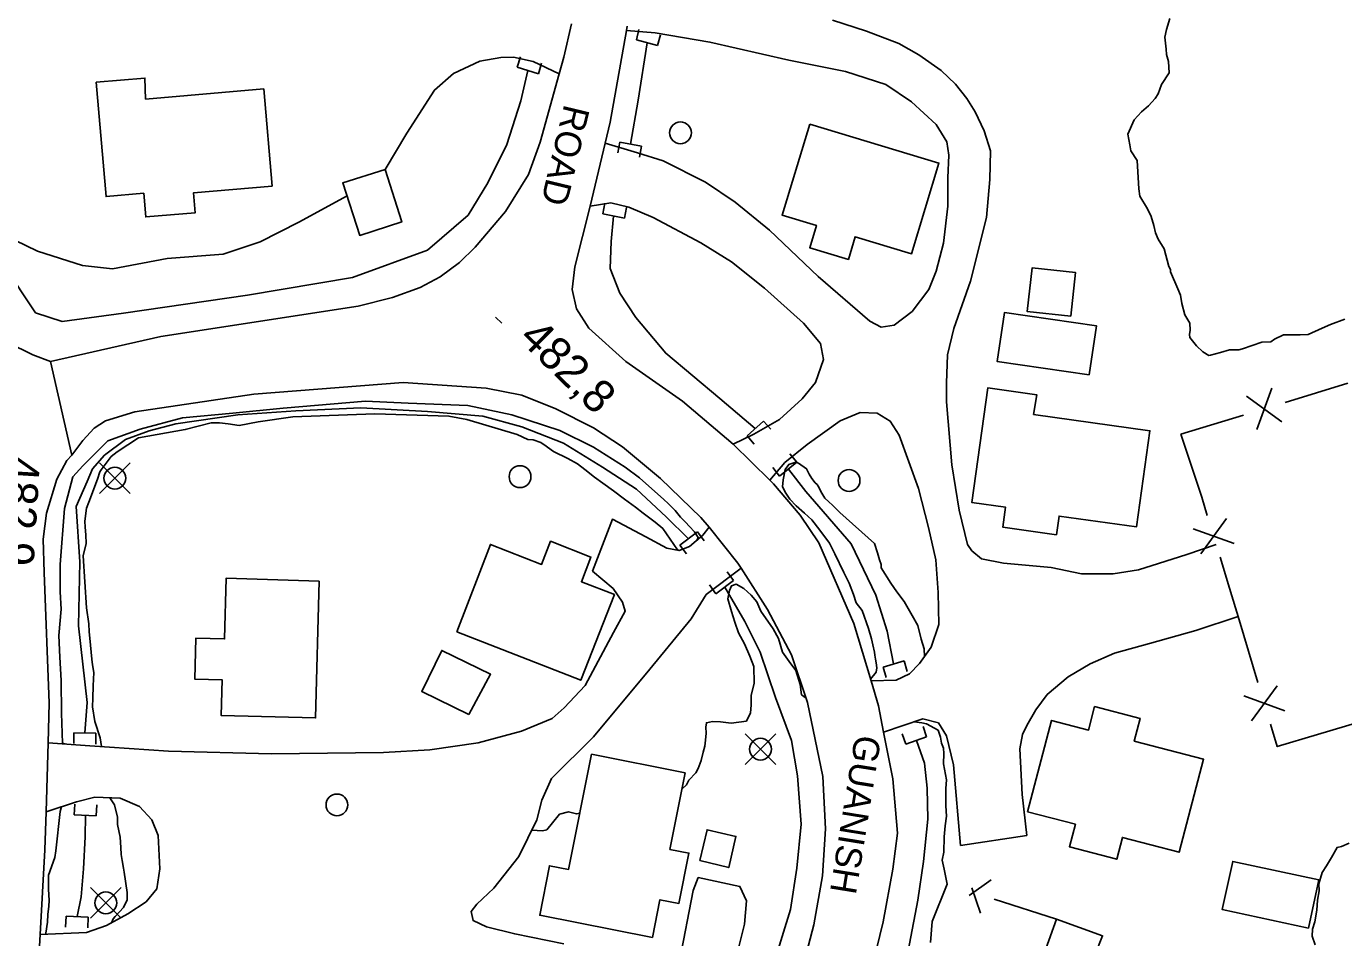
# Model space of a CAD drawing. Extents: x 642515 to 647219, y 6080136 to 6084356.
# Drawn here: x 643828.9 to 643949.6, y 6081952.1 to 6082035.7 of the extents above; entities that cross this region are included whole.
import ezdxf

# ---------------------------------------------------------------- set-up
doc = ezdxf.new("R2010")
doc.units = 0
for name, color, linetype in [('Level 19', 7, 'Continuous'), ('Level 2', 7, 'Continuous'), ('Level 21', 7, 'Continuous'), ('Level 26', 7, 'Continuous'), ('Level 3', 7, 'Continuous'), ('Level 31', 7, 'Continuous'), ('Level 36', 7, 'Continuous'), ('Level 37', 7, 'Continuous'), ('Level 4', 7, 'Continuous')]:
    doc.layers.add(name, color=color, linetype=linetype)

msp = doc.modelspace()

# ---------------------------------------------------------------- linework, layer by layer
at = {"layer": 'Level 19'}
for points in [[(643881.95, 6082024.95), (643884.92, 6082024.05), (643887.27, 6082023.33), (643891.14, 6082021.38), (643893.87, 6082019.55), (643897.01, 6082016.96), (643901.45, 6082012.74), (643906.21, 6082008.63), (643907.25, 6082008.08), (643908.42, 6082008.26), (643910.09, 6082009.52), (643911.6, 6082011.54), (643912.28, 6082013.23), (643912.95, 6082015.77), (643913.33, 6082019.18), (643913.35, 6082021.77), (643913.45, 6082023.84), (643913.26, 6082025.08), (643912.28, 6082026.65), (643910.02, 6082028.75), (643907.67, 6082030.33), (643903.96, 6082031.51), (643898.76, 6082032.57), (643891.54, 6082034.22), (643886.51, 6082035.05), (643883.89, 6082035.29)], [(643902.79, 6082036.23), (643905.88, 6082035.22), (643908.86, 6082034.08), (643910.7, 6082033.05), (643912.72, 6082031.61), (643914.04, 6082030.35), (643915.09, 6082029.03), (643915.84, 6082027.82), (643916.66, 6082026.08), (643917.25, 6082024.25), (643917.19, 6082021.62), (643916.89, 6082018.13), (643915.43, 6082012.31), (643913.88, 6082007.95), (643913.32, 6082005.54), (643913.22, 6082002.94), (643913.23, 6082001.25), (643913.71, 6081995.45), (643914.37, 6081991.32), (643915.15, 6081988.17), (643915.55, 6081987.58), (643916.44, 6081986.86), (643918.45, 6081986.44), (643922.8, 6081986.06), (643925.59, 6081985.48), (643928.5, 6081985.47), (643930.83, 6081985.83), (643932.66, 6081986.41), (643935.25, 6081987.24), (643937.93, 6081988.17)], [(643877.72, 6082031.3), (643875.35, 6082032.43), (643873.55, 6082032.82), (643872.38, 6082032.8), (643870.45, 6082032.46), (643868.04, 6082031.32), (643866.3, 6082029.82), (643863.76, 6082025.88), (643861.77, 6082022.52)], [(643822.51, 6082015.1), (643824.98, 6082017.33), (643826.4, 6082017.37), (643827.85, 6082016.07), (643829.93, 6082015.04), (643834.05, 6082013.72), (643836.78, 6082013.42), (643841.79, 6082014.37), (643846.92, 6082014.76), (643850.34, 6082015.9), (643853.88, 6082017.71), (643858.29, 6082020.11)], [(643893.66, 6081997.37), (643895.56, 6081998.28), (643897.91, 6081999.62), (643900, 6082001.5), (643901.21, 6082003.02), (643901.95, 6082005.12), (643901.67, 6082006.6), (643900.11, 6082008.46), (643896.53, 6082011.67), (643893.53, 6082014.06), (643890.72, 6082015.82), (643886.34, 6082018.13), (643884.1, 6082019.07), (643882.46, 6082019.47), (643880.56, 6082019.17)], [(643906.31, 6081975.65), (643908.61, 6081975.73), (643909.84, 6081976.32), (643910.76, 6081977.25), (643911.81, 6081978.76), (643912.51, 6081980.82), (643912.47, 6081983.77), (643912.23, 6081986.75), (643911.58, 6081989.71), (643910.66, 6081993.29), (643908.9, 6081998.18), (643908.06, 6081999.47), (643906.88, 6082000.21), (643905.3, 6082000.25), (643903.48, 6081999.51), (643900.44, 6081997.33), (643898.42, 6081995.69), (643897.04, 6081994.07)], [(643830.89, 6081969.99), (643834.71, 6081969.71), (643841.91, 6081969.23), (643851.36, 6081968.96), (643861.64, 6081969.09), (643865.88, 6081969.35), (643870.3, 6081969.99), (643874.26, 6081971.04), (643877.07, 6081972.2), (643878.19, 6081973.19), (643880.11, 6081975.23), (643882.72, 6081980.09), (643883.79, 6081982.05), (643883.54, 6081982.88), (643882.66, 6081984.13), (643880.79, 6081985.73), (643882.6, 6081990.47), (643885.68, 6081988.86), (643887.6, 6081987.82), (643888.71, 6081987.6), (643889.66, 6081987.97), (643890.9, 6081989.01), (643891.46, 6081989.74)], [(643894.4, 6081986), (643891.21, 6081983.57), (643889.83, 6081981.36), (643886.03, 6081976.72), (643880.86, 6081970.54), (643877.02, 6081966.71), (643876.15, 6081964.72), (643875.68, 6081962.92), (643874.04, 6081959.56), (643871.73, 6081956.65), (643870.19, 6081955.2), (643869.66, 6081954.52), (643869.83, 6081953.68), (643871.07, 6081953.1), (643873.66, 6081952.47), (643878.16, 6081951.57)], [(643907.46, 6081970.95), (643911.04, 6081972.19), (643912.48, 6081971.82), (643913.23, 6081970.61), (643913.86, 6081967.97), (643914.51, 6081960.57), (643920.57, 6081961.49), (643920.17, 6081965.23), (643919.94, 6081969.42), (643920.19, 6081970.73), (643920.57, 6081971.56), (643921.42, 6081973.02), (643922.44, 6081974.4), (643924.38, 6081976.04), (643926.38, 6081977.23), (643928.63, 6081978.2), (643931.83, 6081979.09), (643936.06, 6081980.28), (643939.94, 6081981.56)], [(643830.16, 6081952.4), (643834.4, 6081952.58), (643836.23, 6081953.24), (643838.2, 6081954.31), (643839.88, 6081955.41), (643840.87, 6081956.6), (643841.13, 6081958.43), (643840.97, 6081961.49), (643840.4, 6081962.92), (643839.28, 6081964.15), (643837.5, 6081964.91), (643835.18, 6081964.99), (643833.5, 6081964.58), (643830.7, 6081963.67)], [(643888.74, 6081949.98), (643890.01, 6081956.43), (643890.47, 6081957.63), (643894.29, 6081956.82), (643894.88, 6081955.51), (643894.72, 6081953.36), (643893.95, 6081950.29)]]:
    msp.add_lwpolyline(points, dxfattribs=at)
at = {"layer": 'Level 2'}
for points in [[(643933.7, 6082036.37), (643933.39, 6082035.36), (643933.22, 6082034.67), (643933.35, 6082033.56), (643933.37, 6082033.08), (643933.57, 6082032.45), (643933.62, 6082031.41), (643932.94, 6082030.34), (643932.62, 6082029.48), (643932.36, 6082029.03), (643931.74, 6082028.36), (643931.09, 6082027.81), (643930.43, 6082027.09), (643929.85, 6082025.78), (643930.02, 6082024.8), (643930.13, 6082024.24)], [(643930.13, 6082024.24), (643930.69, 6082023.35), (643930.86, 6082020.77), (643930.93, 6082020.09), (643931.63, 6082018.93), (643931.98, 6082018.23), (643932.23, 6082017.41), (643932.38, 6082016.73), (643932.61, 6082016.15), (643933.17, 6082015.26), (643933.61, 6082013.65), (643933.75, 6082013.37), (643933.76, 6082013.14), (643934.43, 6082011.61), (643934.66, 6082011.03), (643934.78, 6082010.24), (643935.07, 6082009.21), (643935.51, 6082008.44), (643935.54, 6082007.8), (643935.48, 6082007.4), (643935.53, 6082007.12), (643936.14, 6082006.36), (643936.72, 6082005.83), (643937.26, 6082005.5), (643937.43, 6082005.51), (643938.34, 6082005.75), (643939.17, 6082006), (643940.02, 6082006), (643940.34, 6082006.1), (643942.12, 6082006.71), (643942.93, 6082006.75), (643943.28, 6082006.97), (643944.11, 6082007.37), (643945.64, 6082007.38), (643946.36, 6082007.41), (643947.66, 6082008), (643948.41, 6082008.32), (643949.72, 6082008.83)], [(643832.44, 6081969.88), (643832.21, 6081969.94), (643832.11, 6081972.69), (643832.09, 6081975.68), (643831.98, 6081977.82), (643831.89, 6081979.81), (643832.09, 6081982.22), (643832.01, 6081983.81), (643832.01, 6081986.32), (643832.4, 6081991.45), (643833.15, 6081994.36), (643834.07, 6081995.37), (643836.37, 6081997.65), (643839.34, 6081998.72), (643843.2, 6081999.76), (643847.82, 6082000.21), (643852.43, 6082000.65), (643859.98, 6082001.29), (643863.9, 6082001.13), (643869.35, 6082000.9), (643873.38, 6082000.04), (643877.8, 6081998.6), (643880.86, 6081997.08), (643883.77, 6081995.24), (643885.1, 6081994.27)], [(643888.76, 6081987.62), (643888.57, 6081987.67), (643887.22, 6081989.64), (643886.51, 6081990.2), (643885.42, 6081991.02), (643884.71, 6081991.58), (643883.71, 6081992.32), (643882.7, 6081993.07), (643881.74, 6081993.78), (643880.95, 6081994.33), (643880.07, 6081995.04), (643879.4, 6081995.57), (643878.53, 6081996.04), (643877.21, 6081996.69), (643876.33, 6081997.32), (643876.08, 6081997.47), (643876.04, 6081997.5), (643875.34, 6081997.75), (643874.86, 6081997.8), (643873.87, 6081998.23), (643869.25, 6081999.62), (643867.62, 6081999.93), (643860.84, 6082000.13), (643853.32, 6081999.86), (643850.15, 6081999.41), (643848.4, 6081999.08), (643847.38, 6081999.22), (643846.61, 6081999.3), (643845.85, 6081999.3), (643843.46, 6081998.7), (643839.18, 6081997.95), (643837.23, 6081996.65), (643836.68, 6081996.23), (643835.74, 6081995.02), (643835.62, 6081994.81), (643835.41, 6081994.16), (643834.63, 6081992.05), (643834.42, 6081991.48), (643834.27, 6081990.31), (643834.3, 6081989.76), (643834.34, 6081989.04), (643834.37, 6081988.24), (643834.11, 6081987.11), (643834.42, 6081982.34), (643834.61, 6081980.88), (643834.65, 6081980.16), (643834.72, 6081979.56), (643834.89, 6081977.66), (643834.96, 6081977.14), (643835.07, 6081976.43), (643835.01, 6081975.19), (643834.99, 6081974.07), (643834.95, 6081973.27), (643835.17, 6081971.93), (643835.65, 6081970.44), (643835.77, 6081969.65), (643835.76, 6081969.64)], [(643911.2, 6081977.88), (643911.19, 6081978.61), (643910.91, 6081979.47), (643910.6, 6081980.73), (643910.08, 6081981.66), (643909.33, 6081982.94), (643908.68, 6081983.82), (643908.12, 6081984.63), (643907.25, 6081986.02), (643907.23, 6081986.34), (643907.09, 6081986.77), (643906.9, 6081987.39), (643906.62, 6081988.26), (643903.46, 6081991.08), (643902.78, 6081991.77), (643902.44, 6081992.07), (643902.07, 6081992.41), (643901.71, 6081993.03), (643901.54, 6081993.34), (643901.36, 6081993.65), (643901.19, 6081993.8), (643900.89, 6081994.22), (643900.63, 6081994.6), (643900.4, 6081995.11), (643899.65, 6081995.63), (643899.41, 6081995.7), (643898.77, 6081995.5), (643898.43, 6081995.05), (643898.24, 6081994.08), (643898.19, 6081993.44), (643898.5, 6081992.86), (643898.85, 6081992.32), (643899.44, 6081991.71), (643900.2, 6081991.03), (643900.87, 6081990.43), (643901.6, 6081989.47), (643902.51, 6081988.28), (643903, 6081987.31), (643903.8, 6081985.6), (643904.29, 6081984.62), (643904.71, 6081983.57), (643904.94, 6081982.82), (643905.5, 6081982.1), (643906.06, 6081980.45), (643906.35, 6081979.51), (643906.46, 6081978.96), (643906.61, 6081978.29), (643906.66, 6081978.01), (643906.72, 6081977.65), (643906.78, 6081977.3), (643906.84, 6081976.86), (643906.78, 6081976.46), (643906.26, 6081975.81)], [(643885.1, 6081994.27), (643886.49, 6081993.03), (643887.29, 6081992.31), (643887.76, 6081991.9), (643888.35, 6081991.29), (643888.86, 6081990.68), (643889.29, 6081990.22), (643889.67, 6081989.81), (643890.14, 6081989.31), (643890.45, 6081988.81), (643890.33, 6081988.53)], [(643900.35, 6081974.08), (643899.92, 6081974.39), (643899.8, 6081975.34), (643899.41, 6081976.6), (643898.81, 6081977.44), (643898.2, 6081978.29), (643897.82, 6081979.55), (643897.34, 6081980.44), (643896.21, 6081982.05), (643895.85, 6081982.91), (643895.33, 6081983.52), (643894.66, 6081984.12), (643893.96, 6081984.53), (643893.52, 6081984.38), (643893.34, 6081983.94), (643893.18, 6081983.17), (643893.51, 6081982.03), (643893.84, 6081981.05), (643894.17, 6081980.07), (643894.7, 6081979.06), (643895.2, 6081977.93), (643895.57, 6081976.99), (643895.6, 6081975.44), (643895.33, 6081974.31), (643895.33, 6081973.47), (643895.25, 6081972.71), (643894.99, 6081972.18), (643894.88, 6081971.97), (643893.48, 6081971.78), (643892.51, 6081971.89), (643891.78, 6081971.93), (643891.22, 6081971.82), (643891.16, 6081971.42), (643891.19, 6081970.86), (643891.14, 6081970.22), (643891.09, 6081969.66), (643890.91, 6081969.13), (643890.75, 6081968.37), (643890.46, 6081967.63), (643890.24, 6081967.22), (643889.62, 6081966.55), (643889.4, 6081966.14), (643888.96, 6081965.72)], [(643911.75, 6081951.69), (643911.9, 6081953.61), (643913.27, 6081957.03), (643913, 6081958.41), (643912.84, 6081959.24), (643912.97, 6081959.96), (643913.02, 6081961.36), (643913.09, 6081962.36), (643913.21, 6081963.25), (643913.17, 6081964.2), (643913.17, 6081965.04), (643913.17, 6081965.79), (643913.21, 6081966.59), (643912.94, 6081968.05), (643912.98, 6081969.01), (643912.95, 6081969.49), (643912.77, 6081969.96), (643912.66, 6081970.51), (643912.47, 6081971.14), (643911.4, 6081971.72), (643910.95, 6081971.82), (643910.26, 6081971.9), (643910.25, 6081971.91)], [(643832.13, 6081964.13), (643831.99, 6081963.68), (643831.6, 6081960.07), (643831.51, 6081959.46), (643830.94, 6081957.84), (643830.92, 6081956.56), (643830.98, 6081955.53), (643830.96, 6081955.01), (643830.88, 6081954.25), (643830.83, 6081953.53), (643830.68, 6081952.53), (643830.68, 6081952.42)], [(643836.69, 6081953.49), (643836.86, 6081953.85), (643837.05, 6081954.06), (643837.43, 6081954.48), (643837.81, 6081954.89), (643838.14, 6081955.59), (643838.15, 6081956.27), (643837.86, 6081958.13), (643837.8, 6081958.48), (643837.68, 6081959.19), (643837.58, 6081959.75), (643837.55, 6081960.38), (643837.5, 6081961.34), (643837.24, 6081962.48), (643837.25, 6081963.16), (643836.99, 6081964.3), (643836.54, 6081964.94)], [(643879.62, 6081963.53), (643879.3, 6081963.46), (643878.57, 6081963.66), (643877.77, 6081963.45), (643877.12, 6081962.66), (643876.59, 6081962), (643876.19, 6081961.9), (643875.22, 6081961.98)], [(643950.13, 6081960.77), (643949.42, 6081960.49), (643949.02, 6081960.39), (643948.5, 6081959.47), (643948.06, 6081958.72), (643947.65, 6081958.09), (643947.34, 6081957.06), (643947.38, 6081956.42), (643947.22, 6081955.56), (643947.15, 6081954.63), (643946.97, 6081953.57), (643946.76, 6081952.91), (643946.72, 6081952.26), (643947.01, 6081951.47)]]:
    msp.add_lwpolyline(points, dxfattribs=at)
at = {"layer": 'Level 21'}
for points in [[(643831.1, 6082004.95), (643841.22, 6082007.22), (643859.3, 6082010.02), (643862.46, 6082010.79), (643865, 6082011.73), (643866.81, 6082012.71), (643868.6, 6082014.02), (643870.02, 6082015.43), (643872.8, 6082018.68), (643874.93, 6082022.07), (643875.98, 6082025.04), (643877.72, 6082031.3), (643878.15, 6082032.83), (643878.85, 6082035.88)], [(643883.96, 6082035.68), (643883.89, 6082035.29), (643882.41, 6082026.87), (643881.95, 6082024.95), (643880.56, 6082019.17), (643879.17, 6082013.6), (643878.91, 6082011.52), (643879.33, 6082009.77), (643880.44, 6082008), (643883.85, 6082004.95), (643889.03, 6082001.3), (643893.66, 6081997.37), (643897.04, 6081994.07), (643897.38, 6081993.73), (643899.81, 6081990.86), (643901.53, 6081988.32), (643904.72, 6081980.93), (643906.31, 6081975.65), (643907, 6081973.37), (643907.46, 6081970.95), (643908.29, 6081966.68), (643908.72, 6081961.69), (643908.29, 6081958.4), (643907.42, 6081953.58), (643906.48, 6081949.7)], [(643827.19, 6082006.69), (643829.48, 6082005.55), (643831.1, 6082004.95), (643833.07, 6081996.36), (643832.61, 6081995.85), (643831.69, 6081994.14), (643830.73, 6081991.02), (643830.45, 6081988.66), (643830.54, 6081985.59), (643830.99, 6081973.61), (643830.89, 6081969.99), (643830.7, 6081963.67), (643830.6, 6081960.17), (643830.16, 6081952.4), (643829.86, 6081947.04), (643829.74, 6081945.54), (643828.98, 6081935.8), (643827.49, 6081926.03)], [(643899.43, 6081947.01), (643901.06, 6081953.31), (643901.87, 6081957.8), (643902.12, 6081962.09), (643901.9, 6081966.89), (643900.48, 6081973.69), (643899.03, 6081978.06), (643896.82, 6081982.19), (643894.4, 6081986), (643894.11, 6081986.46), (643891.46, 6081989.74), (643890.72, 6081990.65), (643887.01, 6081994.22), (643883.53, 6081997.11), (643880.88, 6081998.87), (643877.42, 6082000.59), (643874.31, 6082001.84), (643871.04, 6082002.48), (643863.43, 6082003.02), (643849.76, 6082001.94), (643838.83, 6082000.32), (643836.16, 6081999.49), (643835.1, 6081998.83), (643834.07, 6081997.69), (643833.07, 6081996.36)]]:
    msp.add_lwpolyline(points, dxfattribs=at)
at = {"layer": 'Level 26'}
for p, q in [((643884.8, 6082034.42), (643885.04, 6082035.38)), ((643886.74, 6082033.9), (643884.8, 6082034.42)), ((643886.74, 6082033.9), (643887, 6082034.88)), ((643873.88, 6082031.91), (643874.18, 6082032.87)), ((643875.82, 6082031.31), (643873.88, 6082031.91)), ((643875.82, 6082031.31), (643876.12, 6082032.27)), ((643883.28, 6082025.04), (643883.1, 6082024.06)), ((643883.28, 6082025.04), (643885.26, 6082024.66)), ((643885.26, 6082024.66), (643885.08, 6082023.68)), ((643881.72, 6082018.48), (643881.92, 6082019.44)), ((643883.7, 6082018.06), (643881.72, 6082018.48)), ((643883.7, 6082018.06), (643883.9, 6082019.04)), ((643894.95, 6081998.13), (643896.45, 6081999.47)), ((643896.45, 6081999.47), (643897.11, 6081998.73)), ((643894.95, 6081998.13), (643895.61, 6081997.37)), ((643899.51, 6081995.71), (643897.93, 6081994.43)), ((643899.51, 6081995.71), (643898.87, 6081996.47)), ((643897.93, 6081994.43), (643897.31, 6081995.21)), ((643888.79, 6081988.09), (643890.41, 6081989.31)), ((643890.41, 6081989.31), (643891.01, 6081988.51)), ((643888.79, 6081988.09), (643889.41, 6081987.29)), ((643893.71, 6081984.85), (643892.09, 6081983.65)), ((643893.71, 6081984.85), (643893.13, 6081985.65)), ((643892.09, 6081983.65), (643891.49, 6081984.45)), ((643907.41, 6081976.93), (643909.35, 6081977.49)), ((643909.35, 6081977.49), (643909.63, 6081976.53)), ((643907.41, 6081976.93), (643907.69, 6081975.97)), ((643911.4, 6081970.52), (643911.08, 6081971.48)), ((643833.26, 6081970.91), (643833.24, 6081969.91)), ((643833.26, 6081970.91), (643835.28, 6081970.87)), ((643835.28, 6081970.87), (643835.26, 6081969.87)), ((643909.5, 6081969.86), (643909.16, 6081970.8)), ((643911.4, 6081970.52), (643909.5, 6081969.86)), ((643833.29, 6081963.37), (643833.33, 6081964.37)), ((643835.31, 6081963.29), (643835.35, 6081964.29)), ((643835.31, 6081963.29), (643833.29, 6081963.37)), ((643832.54, 6081954.09), (643832.5, 6081953.09)), ((643832.54, 6081954.09), (643834.56, 6081954.01)), ((643834.56, 6081954.01), (643834.52, 6081953.01))]:
    msp.add_line(p, q, dxfattribs=at)
at = {"layer": 'Level 3'}
msp.add_line((643871.9, 6082009.01), (643872.47, 6082008.45), dxfattribs=at)
at = {"layer": 'Level 31'}
for points in [[(643839.83, 6082028.99), (643850.65, 6082029.92), (643851.41, 6082021.01), (643844.23, 6082020.4), (643844.38, 6082018.57), (643839.84, 6082018.19), (643839.66, 6082020.36), (643836.2, 6082020.06), (643835.3, 6082030.53), (643839.76, 6082030.91), (643839.83, 6082028.99)], [(643900.69, 6082026.68), (643912.53, 6082023.13), (643910.03, 6082014.81), (643904.85, 6082016.37), (643904.23, 6082014.3), (643900.69, 6082015.36), (643901.3, 6082017.41), (643898.16, 6082018.35), (643900.69, 6082026.68)], [(643861.77, 6082022.52), (643863.3, 6082017.73), (643859.45, 6082016.5), (643857.9, 6082021.32), (643861.77, 6082022.52)], [(643924.61, 6082009.08), (643920.63, 6082009.51), (643921.07, 6082013.52), (643925.05, 6082013.08), (643924.61, 6082009.08)], [(643926.31, 6082003.71), (643917.88, 6082004.92), (643918.53, 6082009.42), (643926.96, 6082008.21), (643926.31, 6082003.71)], [(643921.2, 6082000.09), (643931.86, 6081998.58), (643930.62, 6081989.77), (643923.54, 6081990.77), (643923.3, 6081989.05), (643918.38, 6081989.75), (643918.64, 6081991.58), (643915.53, 6081992.02), (643917.01, 6082002.51), (643921.49, 6082001.88), (643921.2, 6082000.09)], [(643868.36, 6081980.17), (643879.71, 6081975.72), (643882.79, 6081983.57), (643879.76, 6081984.75), (643880.64, 6081987.01), (643876.94, 6081988.46), (643876.11, 6081986.34), (643871.43, 6081988.17), (643868.36, 6081980.17)], [(643855.73, 6081984.8), (643855.4, 6081972.26), (643846.74, 6081972.49), (643846.83, 6081975.77), (643844.33, 6081975.83), (643844.43, 6081979.58), (643847.06, 6081979.51), (643847.2, 6081985.07), (643855.73, 6081984.8)], [(643869.46, 6081972.59), (643865.14, 6081974.7), (643866.97, 6081978.45), (643871.44, 6081976.27), (643869.46, 6081972.59)], [(643920.65, 6081963.67), (643925.03, 6081962.52), (643924.49, 6081960.45), (643928.83, 6081959.31), (643929.35, 6081961.31), (643934.55, 6081959.95), (643936.78, 6081968.48), (643930.43, 6081970.14), (643930.98, 6081972.22), (643926.8, 6081973.31), (643926.24, 6081971.15), (643922.85, 6081972.04), (643920.65, 6081963.67)], [(643889.26, 6081967.24), (643880.69, 6081968.94), (643878.59, 6081958.37), (643876.84, 6081958.72), (643875.95, 6081954.18), (643886.27, 6081952.14), (643886.96, 6081955.6), (643888.7, 6081955.26), (643889.61, 6081959.87), (643887.87, 6081960.21), (643889.26, 6081967.24)], [(643890.63, 6081959.2), (643891.28, 6081962.02), (643893.93, 6081961.4), (643893.27, 6081958.55), (643890.63, 6081959.2)], [(643946.4, 6081952.99), (643938.5, 6081954.69), (643939.45, 6081959.11), (643947.35, 6081957.41), (643946.4, 6081952.99)], [(643926.83, 6081950.53), (643936.96, 6081946.91), (643933.97, 6081938.52), (643927.15, 6081940.95), (643926.57, 6081939.31), (643922.26, 6081940.84), (643922.87, 6081942.55), (643919.67, 6081943.69), (643923.29, 6081953.81), (643927.52, 6081952.29), (643926.83, 6081950.53)]]:
    msp.add_lwpolyline(points, dxfattribs=at)
at = {"layer": 'Level 36'}
for p, q in [((643838.42, 6081992.83), (643835.6, 6081995.65)), ((643835.6, 6081992.83), (643838.42, 6081995.65)), ((643897.59, 6081967.99), (643894.77, 6081970.81)), ((643894.77, 6081967.99), (643897.59, 6081970.81)), ((643837.59, 6081953.9), (643834.77, 6081956.72)), ((643834.77, 6081953.9), (643837.59, 6081956.72))]:
    msp.add_line(p, q, dxfattribs=at)
for centre in [(643888.84, 6082025.9), (643837.01, 6081994.24), (643874.14, 6081994.38), (643904.29, 6081994.03), (643896.18, 6081969.4), (643857.36, 6081964.29), (643836.18, 6081955.31)]:
    msp.add_circle(centre, 1, dxfattribs=at)
at = {"layer": 'Level 37'}
for p, q in [((643944.26, 6082001.19), (643950, 6082002.94)), ((643940.73, 6082001.77), (643943.96, 6081999.42)), ((643943.03, 6082002.48), (643941.67, 6081998.71)), ((643934.7, 6081998.26), (643940.44, 6082000.02)), ((643935.27, 6081996.54), (643934.7, 6081998.26)), ((643935.83, 6081989.59), (643939.59, 6081988.24)), ((643936.53, 6081987.3), (643938.89, 6081990.53)), ((643941.76, 6081975.52), (643940.04, 6081981.27)), ((643941.16, 6081971.99), (643943.53, 6081975.21)), ((643940.47, 6081974.29), (643944.22, 6081972.91)), ((643952.98, 6081972.47), (643947.23, 6081970.75)), ((643915.31, 6081956), (643917.31, 6081957.42)), ((643916.33, 6081954.37), (643915.53, 6081956.69)), ((643923.29, 6081953.81), (643917.58, 6081955.65))]:
    msp.add_line(p, q, dxfattribs=at)
for points in [[(643937.12, 6081990.83), (643936.61, 6081992.49), (643935.27, 6081996.54)], [(643940.04, 6081981.27), (643939.17, 6081984.15), (643938.29, 6081987.01)], [(643947.23, 6081970.75), (643943.53, 6081969.64), (643942.91, 6081971.69)]]:
    msp.add_lwpolyline(points, dxfattribs=at)
at = {"layer": 'Level 4'}
for points in [[(643885.78, 6082034.16), (643884.98, 6082028.9), (643884.26, 6082024.86)], [(643874.86, 6082031.61), (643874.2, 6082028.83), (643872.92, 6082024.84), (643871.2, 6082021.31), (643869.38, 6082018.34), (643865.66, 6082015.15), (643858.79, 6082012.65), (643849.15, 6082011.02), (643837.8, 6082009.38), (643832.17, 6082008.6), (643829.74, 6082009.4), (643826.82, 6082013.78), (643825.48, 6082015.86)], [(643882.72, 6082018.26), (643882.48, 6082015.94), (643882.41, 6082013.47), (643883.3, 6082011.21), (643884.76, 6082008.98), (643887.5, 6082005.69), (643892.46, 6082001.53), (643895.69, 6081998.79)], [(643889.59, 6081988.69), (643887.54, 6081990.69), (643884.81, 6081993.22), (643881.7, 6081995.24), (643878.13, 6081997.44), (643874.32, 6081998.94), (643870.74, 6081999.93), (643865.65, 6082000.35), (643859.55, 6082000.68), (643853.6, 6082000.41), (643848.27, 6082000.05), (643842.6, 6081999.23), (643840.16, 6081998.58), (643837.98, 6081997.78), (643836.07, 6081996.34), (643834.96, 6081995.11), (643834.46, 6081993.95), (643833.45, 6081991.64), (643833.81, 6081986.56), (643833.69, 6081980.69), (643834.48, 6081973.69), (643834.26, 6081970.89)], [(643898.73, 6081995.07), (643900.34, 6081993.01), (643904.49, 6081988.21), (643906.74, 6081983.51), (643907.77, 6081980.21), (643908.37, 6081977.21)], [(643896.67, 6081947.22), (643897.28, 6081949.35), (643898.94, 6081954.7), (643899.5, 6081958.49), (643899.89, 6081962.51), (643899.57, 6081966.95), (643899.03, 6081970.2), (643897.56, 6081974.13), (643896.16, 6081978.3), (643894.75, 6081981.1), (643892.91, 6081984.25)], [(643910.46, 6081970.2), (643911.22, 6081968.13), (643911.46, 6081965.84), (643911.5, 6081962.97), (643911.1, 6081959.11), (643910.6, 6081955.56), (643909.84, 6081951.56), (643909.35, 6081948.7)], [(643834.31, 6081963.33), (643834.3, 6081961.35), (643834.13, 6081958.43), (643833.91, 6081955.87), (643833.54, 6081954.05)]]:
    msp.add_lwpolyline(points, dxfattribs=at)

# ---------------------------------------------------------------- texts
at = {"layer": 'Level 21'}
for s, rotation, p in [('ROAD', 256.4622, (643878.21, 6082028.6)), ('GUANISH', 260.831, (643904.87, 6081970.8))]:
    msp.add_text(s, height=2.4, rotation=rotation, dxfattribs=at).set_placement(p)
at = {"layer": 'Level 3'}
for s, rotation, p in [('482,8', 315.59, (643873.93, 6082006.96)), ('482,9', 266.5169, (643827.17, 6081996.3))]:
    msp.add_text(s, height=3, rotation=rotation, dxfattribs=at).set_placement(p)

doc.saveas('drawing.dxf')
